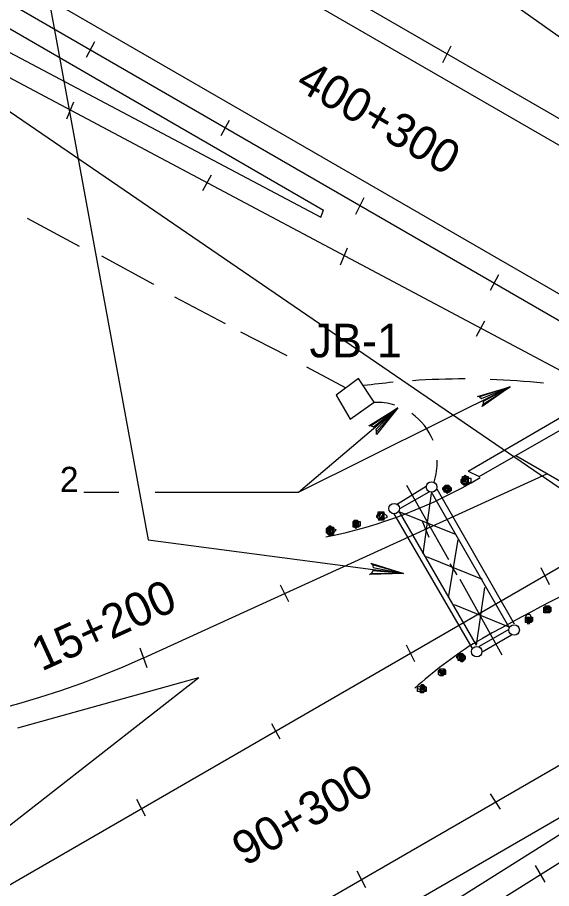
# Model space of a CAD drawing. Extents: x 36 to 2622, y -5330 to 219.
# Drawn here: x 2003.5 to 2051, y -4415.8 to -4338.2 of the extents above; entities that cross this region are included whole.
import ezdxf

# ---------------------------------------------------------------- set-up
doc = ezdxf.new("R2010")
doc.units = 0
doc.layers.add('2', color=7, linetype='Continuous')
doc.layers.add('3', color=7, linetype='Continuous')

# ---------------------------------------------------------------- blocks, each defined once
blk = doc.blocks.new('RARROW')
at = {"layer": '3'}
blk.add_lwpolyline([(-2.2695, 0.285), (-2.184875, 0.12075), (0, 0), (-2.2695, 0.285), (-2.38575, 0.384625), (0, 0), (-2.183125, -0.108), (-2.262875, -0.2705), (0, 0), (-2.38575, -0.379125), (-2.262875, -0.2705)], dxfattribs=at)

msp = doc.modelspace()

# ---------------------------------------------------------------- linework, layer by layer
at = {"layer": '2'}
for p, q in [((1732.847, -4161.874), (2538.009, -4712.774)), ((1828.856, -4218.455), (2074.481, -4360.33)), ((1984.731, -4219.33), (2015.106, -4384.705)), ((1827.856, -4220.205), (2072.731, -4361.705)), ((1822.106, -4230.205), (2060.856, -4368.08)), ((1820.981, -4231.955), (2055.231, -4367.205)), ((1954.606, -4443.205), (2241.981, -4277.33)), ((1905.981, -4283.33), (2030.731, -4355.33)), ((1962.231, -4456.455), (2237.606, -4297.455)), ((2078.106, -4358.705), (2040.356, -4331.83)), ((1996.856, -4338.205), (2030.481, -4355.955)), ((1995.981, -4339.955), (2055.481, -4371.58)), ((2009.606, -4341.705), (2010.356, -4340.33)), ((2041.356, -4342.205), (2042.106, -4340.705)), ((2007.856, -4347.205), (2008.481, -4345.705)), ((2021.606, -4348.705), (2022.356, -4347.33)), ((2043.606, -4378.58), (2091.606, -4350.705)), ((2044.606, -4379.08), (2092.731, -4351.455)), ((2019.981, -4353.58), (2020.731, -4352.205)), ((2033.606, -4355.705), (2034.356, -4354.205)), ((2030.481, -4355.955), (2030.731, -4355.33)), ((2008.981, -4358.58), (2004.356, -4356.08)), ((2032.231, -4360.205), (2032.856, -4358.705)), ((2015.606, -4361.955), (2010.981, -4359.455)), ((2045.606, -4362.455), (2046.356, -4361.08)), ((2021.981, -4365.455), (2017.481, -4363.08)), ((2044.356, -4366.58), (2045.106, -4365.205)), ((2027.481, -4368.33), (2023.356, -4366.205)), ((2032.731, -4371.205), (2029.231, -4369.33)), ((2028.481, -4380.455), (2047.356, -4371.08)), ((2028.481, -4380.455), (2037.356, -4372.955)), ((2047.856, -4377.205), (2061.231, -4384.955)), ((2014.731, -4395.205), (2050.606, -4378.83)), ((2043.606, -4378.58), (2044.606, -4379.08)), ((2038.106, -4379.83), (2041.856, -4386.455)), ((2009.356, -4380.455), (2012.481, -4380.455)), ((2015.731, -4380.455), (2028.481, -4380.455)), ((2039.856, -4379.955), (2037.231, -4381.58)), ((2040.106, -4380.455), (2037.481, -4381.955)), ((2039.606, -4385.955), (2040.356, -4380.58)), ((2047.231, -4392.455), (2040.356, -4380.455)), ((2047.731, -4392.205), (2040.856, -4380.205)), ((2044.356, -4394.08), (2037.481, -4382.205)), ((2037.481, -4382.205), (2042.481, -4384.205)), ((2043.981, -4394.33), (2036.981, -4382.33)), ((2039.481, -4382.955), (2040.106, -4384.455)), ((2015.106, -4384.705), (2037.856, -4387.705)), ((2041.856, -4389.83), (2042.731, -4384.705)), ((2039.856, -4386.205), (2044.856, -4388.205)), ((2041.981, -4386.83), (2042.606, -4387.83)), ((2050.856, -4388.705), (2050.106, -4387.205)), ((2042.856, -4388.205), (2046.606, -4394.955)), ((2026.856, -4388.705), (2027.606, -4390.205)), ((2044.356, -4394.08), (2045.106, -4388.955)), ((2042.356, -4390.455), (2047.231, -4392.455)), ((2047.231, -4392.705), (2044.606, -4394.205)), ((2047.481, -4393.205), (2044.856, -4394.705)), ((2014.356, -4394.33), (2014.981, -4396.08)), ((2038.856, -4395.58), (2038.106, -4394.08)), ((2038.356, -4421.83), (2080.856, -4395.205)), ((1999.606, -4412.58), (2019.606, -4396.955)), ((2003.481, -4401.455), (2019.606, -4396.955)), ((1964.356, -4459.955), (2068.356, -4399.83)), ((2037.231, -4420.08), (2068.606, -4400.33)), ((2026.856, -4402.455), (2026.106, -4401.08)), ((2014.856, -4409.33), (2014.106, -4407.83)), ((2046.481, -4408.705), (2045.606, -4407.33)), ((2050.481, -4415.205), (2049.606, -4413.705)), ((2034.481, -4415.705), (2033.731, -4414.205))]:
    msp.add_line(p, q, dxfattribs=at)
msp.add_lwpolyline([(2033.106, -4373.955), (2035.231, -4372.455), (2033.856, -4370.33), (2031.856, -4371.83)], close=True, dxfattribs=at)
for points in [[(2043.356, -4379.33), (2043.231, -4379.33), (2043.356, -4379.33), (2043.356, -4379.33), (2043.356, -4379.33), (2043.356, -4379.33), (2043.356, -4379.58), (2043.231, -4379.33), (2043.231, -4379.33), (2043.231, -4379.205), (2043.356, -4379.205), (2043.356, -4379.205), (2043.481, -4379.33), (2043.481, -4379.58), (2043.356, -4379.58), (2043.231, -4379.58), (2043.106, -4379.33), (2043.106, -4379.205), (2043.231, -4379.205), (2043.356, -4379.08), (2043.481, -4379.205), (2043.481, -4379.33), (2043.481, -4379.58), (2043.481, -4379.705), (2043.356, -4379.705), (2043.231, -4379.705), (2043.106, -4379.58), (2043.106, -4379.33), (2043.106, -4379.205), (2043.106, -4379.08), (2043.356, -4379.08), (2043.481, -4379.08), (2043.606, -4379.205), (2043.606, -4379.33), (2043.606, -4379.58), (2043.606, -4379.705), (2043.356, -4379.705), (2043.231, -4379.83), (2043.231, -4379.705), (2043.106, -4379.705), (2042.981, -4379.58), (2042.981, -4379.33), (2042.981, -4379.33), (2043.106, -4379.205), (2043.106, -4379.08), (2043.231, -4379.08), (2043.356, -4378.955), (2043.356, -4378.955), (2043.481, -4379.08), (2043.606, -4379.08), (2043.606, -4379.205), (2043.856, -4379.205), (2043.856, -4379.33), (2043.856, -4379.58), (2043.606, -4379.705), (2043.606, -4379.705), (2043.481, -4379.83), (2043.356, -4379.83), (2043.231, -4379.83), (2043.231, -4379.83), (2043.106, -4379.705)], [(2041.731, -4380.205), (2041.731, -4380.205), (2041.731, -4380.08), (2041.731, -4380.08), (2041.856, -4380.205), (2041.731, -4380.205), (2041.731, -4380.205), (2041.606, -4380.205), (2041.606, -4380.205), (2041.606, -4380.08), (2041.731, -4380.08), (2041.856, -4380.08), (2041.856, -4380.08), (2041.856, -4380.205), (2041.731, -4380.33), (2041.606, -4380.33), (2041.606, -4380.205), (2041.606, -4380.08), (2041.606, -4379.955), (2041.731, -4379.955), (2041.856, -4380.08), (2041.981, -4380.205), (2041.981, -4380.33), (2041.856, -4380.33), (2041.731, -4380.455), (2041.606, -4380.455), (2041.481, -4380.33), (2041.481, -4380.205), (2041.481, -4380.08), (2041.606, -4379.955), (2041.731, -4379.955), (2041.856, -4379.955), (2041.981, -4379.955), (2041.981, -4380.08), (2041.981, -4380.33), (2041.981, -4380.33), (2041.856, -4380.455), (2041.731, -4380.455), (2041.606, -4380.455), (2041.481, -4380.455), (2041.481, -4380.33), (2041.356, -4380.205), (2041.356, -4380.08), (2041.481, -4379.955), (2041.481, -4379.955), (2041.606, -4379.83), (2041.731, -4379.83), (2041.856, -4379.83), (2041.856, -4379.83), (2041.981, -4379.955), (2041.981, -4379.955), (2042.106, -4380.08), (2042.106, -4380.205), (2042.106, -4380.33), (2041.981, -4380.33), (2041.981, -4380.455), (2041.856, -4380.455), (2041.731, -4380.58), (2041.731, -4380.58), (2041.606, -4380.455), (2041.481, -4380.455)], [(2035.856, -4382.58), (2035.856, -4382.58), (2035.856, -4382.58), (2035.856, -4382.58), (2035.981, -4382.58), (2035.981, -4382.705), (2035.856, -4382.705), (2035.731, -4382.705), (2035.731, -4382.58), (2035.731, -4382.58), (2035.856, -4382.33), (2035.981, -4382.33), (2035.981, -4382.58), (2035.981, -4382.705), (2035.856, -4382.83), (2035.731, -4382.705), (2035.731, -4382.705), (2035.731, -4382.58), (2035.731, -4382.33), (2035.981, -4382.33), (2035.981, -4382.33), (2036.106, -4382.58), (2036.106, -4382.705), (2035.981, -4382.83), (2035.856, -4382.83), (2035.731, -4382.83), (2035.606, -4382.83), (2035.606, -4382.705), (2035.606, -4382.58), (2035.731, -4382.33), (2035.856, -4382.205), (2035.981, -4382.205), (2036.106, -4382.33), (2036.106, -4382.58), (2036.106, -4382.705), (2036.106, -4382.83), (2035.981, -4382.955), (2035.856, -4382.955), (2035.731, -4382.955), (2035.606, -4382.83), (2035.606, -4382.705), (2035.481, -4382.705), (2035.481, -4382.58), (2035.606, -4382.33), (2035.606, -4382.205), (2035.731, -4382.205), (2035.856, -4382.205), (2035.981, -4382.205), (2035.981, -4382.205), (2036.106, -4382.205), (2036.106, -4382.33), (2036.356, -4382.58), (2036.356, -4382.705), (2036.356, -4382.705), (2036.106, -4382.83), (2036.106, -4382.955), (2035.981, -4382.955), (2035.856, -4382.955), (2035.856, -4382.955), (2035.731, -4382.955), (2035.606, -4382.955)], [(2033.606, -4383.33), (2033.606, -4383.33), (2033.606, -4383.205), (2033.606, -4383.205), (2033.731, -4383.33), (2033.731, -4383.33), (2033.606, -4383.33), (2033.606, -4383.33), (2033.481, -4383.33), (2033.481, -4383.205), (2033.606, -4383.205), (2033.731, -4383.205), (2033.731, -4383.205), (2033.731, -4383.33), (2033.606, -4383.455), (2033.481, -4383.455), (2033.481, -4383.33), (2033.481, -4383.205), (2033.606, -4383.08), (2033.731, -4383.08), (2033.731, -4383.205), (2033.856, -4383.33), (2033.856, -4383.455), (2033.731, -4383.455), (2033.606, -4383.58), (2033.481, -4383.58), (2033.481, -4383.455), (2033.356, -4383.33), (2033.356, -4383.205), (2033.481, -4383.08), (2033.606, -4383.08), (2033.731, -4383.08), (2033.856, -4383.08), (2033.856, -4383.205), (2033.856, -4383.455), (2033.856, -4383.58), (2033.731, -4383.58), (2033.606, -4383.58), (2033.481, -4383.58), (2033.356, -4383.58), (2033.356, -4383.455), (2033.356, -4383.33), (2033.356, -4383.205), (2033.356, -4383.08), (2033.356, -4383.08), (2033.481, -4382.955), (2033.606, -4382.955), (2033.731, -4382.955), (2033.731, -4382.955), (2033.856, -4383.08), (2033.981, -4383.08), (2033.981, -4383.205), (2033.981, -4383.33), (2033.981, -4383.455), (2033.981, -4383.455), (2033.856, -4383.58), (2033.731, -4383.58), (2033.606, -4383.705), (2033.606, -4383.705), (2033.481, -4383.58), (2033.481, -4383.58)], [(2031.356, -4383.83), (2031.231, -4383.83), (2031.231, -4383.83), (2031.356, -4383.705), (2031.356, -4383.83), (2031.356, -4383.83), (2031.356, -4384.08), (2031.231, -4383.83), (2031.231, -4383.83), (2031.231, -4383.705), (2031.356, -4383.705), (2031.356, -4383.705), (2031.481, -4383.83), (2031.481, -4384.08), (2031.356, -4384.08), (2031.231, -4384.08), (2031.106, -4383.83), (2031.106, -4383.705), (2031.231, -4383.58), (2031.356, -4383.58), (2031.481, -4383.705), (2031.481, -4383.83), (2031.481, -4384.08), (2031.481, -4384.205), (2031.356, -4384.205), (2031.231, -4384.205), (2031.106, -4384.08), (2031.106, -4383.83), (2031.106, -4383.705), (2031.106, -4383.58), (2031.231, -4383.58), (2031.481, -4383.58), (2031.606, -4383.705), (2031.606, -4383.83), (2031.606, -4384.08), (2031.481, -4384.205), (2031.356, -4384.205), (2031.231, -4384.33), (2031.106, -4384.205), (2031.106, -4384.205), (2030.981, -4384.08), (2030.981, -4383.83), (2030.981, -4383.705), (2030.981, -4383.705), (2031.106, -4383.58), (2031.231, -4383.58), (2031.231, -4383.455), (2031.356, -4383.455), (2031.481, -4383.58), (2031.606, -4383.58), (2031.606, -4383.705), (2031.606, -4383.705), (2031.856, -4383.83), (2031.606, -4384.08), (2031.606, -4384.205), (2031.606, -4384.205), (2031.481, -4384.33), (2031.356, -4384.33), (2031.231, -4384.33), (2031.231, -4384.33), (2031.106, -4384.205)], [(2050.731, -4390.955), (2050.606, -4390.955), (2050.606, -4390.83), (2050.731, -4390.83), (2050.731, -4390.83), (2050.731, -4390.955), (2050.606, -4390.955), (2050.606, -4390.955), (2050.481, -4390.83), (2050.606, -4390.83), (2050.606, -4390.83), (2050.731, -4390.83), (2050.731, -4390.83), (2050.731, -4390.955), (2050.731, -4391.08), (2050.606, -4391.08), (2050.481, -4390.955), (2050.481, -4390.83), (2050.606, -4390.705), (2050.731, -4390.705), (2050.856, -4390.83), (2050.856, -4390.955), (2050.856, -4390.955), (2050.731, -4391.08), (2050.731, -4391.08), (2050.606, -4391.08), (2050.481, -4391.08), (2050.356, -4390.955), (2050.356, -4390.83), (2050.481, -4390.705), (2050.606, -4390.58), (2050.731, -4390.705), (2050.856, -4390.705), (2050.981, -4390.83), (2050.981, -4390.955), (2050.856, -4391.08), (2050.731, -4391.205), (2050.606, -4391.205), (2050.481, -4391.205), (2050.356, -4391.205), (2050.356, -4391.08), (2050.356, -4390.955), (2050.356, -4390.83), (2050.356, -4390.705), (2050.481, -4390.705), (2050.481, -4390.58), (2050.606, -4390.58), (2050.731, -4390.58), (2050.856, -4390.58), (2050.856, -4390.705), (2050.981, -4390.705), (2050.981, -4390.83), (2050.981, -4390.955), (2050.981, -4391.08), (2050.981, -4391.08), (2050.856, -4391.205), (2050.731, -4391.205), (2050.731, -4391.205), (2050.606, -4391.205), (2050.481, -4391.205), (2050.481, -4391.205)], [(2048.981, -4391.83), (2048.981, -4391.83), (2048.981, -4391.705), (2048.981, -4391.705), (2049.106, -4391.705), (2049.106, -4391.83), (2048.981, -4391.83), (2048.981, -4391.83), (2048.856, -4391.83), (2048.856, -4391.705), (2048.981, -4391.705), (2049.106, -4391.705), (2049.106, -4391.705), (2049.106, -4391.83), (2048.981, -4391.955), (2048.856, -4391.955), (2048.856, -4391.83), (2048.856, -4391.705), (2048.981, -4391.58), (2049.106, -4391.58), (2049.106, -4391.705), (2049.231, -4391.83), (2049.231, -4391.83), (2049.106, -4391.955), (2048.981, -4392.08), (2048.856, -4392.08), (2048.856, -4391.955), (2048.731, -4391.83), (2048.731, -4391.705), (2048.856, -4391.58), (2048.981, -4391.58), (2049.106, -4391.58), (2049.231, -4391.58), (2049.231, -4391.705), (2049.231, -4391.955), (2049.231, -4391.955), (2049.106, -4392.08), (2048.981, -4392.08), (2048.856, -4392.08), (2048.731, -4392.08), (2048.731, -4391.955), (2048.731, -4391.83), (2048.731, -4391.705), (2048.731, -4391.58), (2048.731, -4391.58), (2048.856, -4391.33), (2048.981, -4391.33), (2049.106, -4391.33), (2049.106, -4391.33), (2049.231, -4391.58), (2049.356, -4391.58), (2049.356, -4391.705), (2049.356, -4391.83), (2049.356, -4391.955), (2049.356, -4391.955), (2049.231, -4392.08), (2049.106, -4392.08), (2048.981, -4392.205), (2048.981, -4392.205), (2048.856, -4392.08), (2048.856, -4392.08)], [(2042.981, -4395.205), (2042.981, -4395.205), (2042.981, -4395.08), (2042.981, -4395.08), (2043.106, -4395.205), (2042.981, -4395.205), (2042.981, -4395.33), (2042.856, -4395.205), (2042.856, -4395.205), (2042.856, -4395.08), (2042.981, -4395.08), (2043.106, -4395.08), (2043.106, -4395.205), (2043.106, -4395.205), (2042.981, -4395.33), (2042.856, -4395.33), (2042.856, -4395.205), (2042.856, -4395.08), (2042.856, -4394.955), (2043.106, -4394.955), (2043.106, -4395.08), (2043.231, -4395.205), (2043.231, -4395.33), (2043.106, -4395.33), (2042.981, -4395.455), (2042.856, -4395.455), (2042.731, -4395.33), (2042.731, -4395.205), (2042.731, -4395.08), (2042.856, -4394.955), (2042.981, -4394.955), (2043.106, -4394.955), (2043.231, -4395.08), (2043.231, -4395.08), (2043.231, -4395.33), (2043.231, -4395.455), (2043.106, -4395.455), (2042.981, -4395.455), (2042.856, -4395.455), (2042.731, -4395.455), (2042.731, -4395.33), (2042.606, -4395.205), (2042.606, -4395.08), (2042.731, -4395.08), (2042.731, -4394.955), (2042.856, -4394.83), (2042.981, -4394.83), (2043.106, -4394.83), (2043.106, -4394.83), (2043.231, -4394.955), (2043.231, -4394.955), (2043.356, -4395.08), (2043.356, -4395.205), (2043.356, -4395.33), (2043.231, -4395.455), (2043.231, -4395.455), (2043.106, -4395.58), (2042.981, -4395.58), (2042.981, -4395.58), (2042.856, -4395.455), (2042.731, -4395.455)], [(2041.231, -4396.455), (2041.231, -4396.455), (2041.231, -4396.455), (2041.356, -4396.455), (2041.356, -4396.455), (2041.356, -4396.58), (2041.231, -4396.58), (2041.231, -4396.58), (2041.106, -4396.455), (2041.231, -4396.33), (2041.231, -4396.33), (2041.356, -4396.33), (2041.356, -4396.455), (2041.356, -4396.58), (2041.356, -4396.58), (2041.231, -4396.58), (2041.106, -4396.58), (2041.106, -4396.33), (2041.231, -4396.33), (2041.356, -4396.33), (2041.481, -4396.33), (2041.481, -4396.455), (2041.481, -4396.58), (2041.356, -4396.705), (2041.231, -4396.705), (2041.231, -4396.705), (2041.106, -4396.58), (2040.981, -4396.455), (2040.981, -4396.455), (2041.106, -4396.33), (2041.231, -4396.205), (2041.356, -4396.205), (2041.481, -4396.33), (2041.481, -4396.455), (2041.606, -4396.58), (2041.481, -4396.705), (2041.356, -4396.83), (2041.231, -4396.83), (2041.106, -4396.83), (2040.981, -4396.705), (2040.981, -4396.58), (2040.981, -4396.58), (2040.981, -4396.455), (2040.981, -4396.33), (2041.106, -4396.205), (2041.106, -4396.205), (2041.231, -4396.205), (2041.356, -4396.205), (2041.481, -4396.205), (2041.481, -4396.205), (2041.606, -4396.33), (2041.606, -4396.455), (2041.606, -4396.58), (2041.606, -4396.58), (2041.606, -4396.705), (2041.481, -4396.705), (2041.356, -4396.83), (2041.356, -4396.83), (2041.231, -4396.83), (2041.106, -4396.83), (2041.106, -4396.705)], [(2039.606, -4397.955), (2039.481, -4397.955), (2039.481, -4397.955), (2039.606, -4397.955), (2039.606, -4397.955), (2039.606, -4397.955), (2039.481, -4398.08), (2039.481, -4397.955), (2039.356, -4397.955), (2039.481, -4397.83), (2039.481, -4397.83), (2039.606, -4397.83), (2039.606, -4397.955), (2039.606, -4398.08), (2039.606, -4398.08), (2039.481, -4398.08), (2039.356, -4397.955), (2039.356, -4397.83), (2039.481, -4397.83), (2039.606, -4397.705), (2039.731, -4397.83), (2039.731, -4397.955), (2039.731, -4398.08), (2039.606, -4398.205), (2039.481, -4398.205), (2039.481, -4398.205), (2039.356, -4398.08), (2039.106, -4397.955), (2039.106, -4397.83), (2039.356, -4397.705), (2039.481, -4397.705), (2039.606, -4397.705), (2039.731, -4397.83), (2039.731, -4397.955), (2039.856, -4398.08), (2039.731, -4398.205), (2039.606, -4398.205), (2039.481, -4398.33), (2039.356, -4398.205), (2039.106, -4398.205), (2039.106, -4398.08), (2039.106, -4397.955), (2039.106, -4397.955), (2039.106, -4397.83), (2039.356, -4397.705), (2039.356, -4397.705), (2039.481, -4397.58), (2039.606, -4397.58), (2039.731, -4397.705), (2039.731, -4397.705), (2039.856, -4397.83), (2039.856, -4397.83), (2039.856, -4397.955), (2039.856, -4398.08), (2039.856, -4398.205), (2039.731, -4398.205), (2039.606, -4398.33), (2039.606, -4398.33), (2039.481, -4398.33), (2039.356, -4398.33), (2039.356, -4398.205)]]:
    msp.add_lwpolyline(points, dxfattribs=at)
for centre in [(2040.351, -4380.001), (2037.019, -4381.925), (2047.706, -4392.739), (2044.374, -4394.663)]:
    msp.add_circle(centre, 0.468, dxfattribs=at)
for centre, radius, start, end in [((2043.223, -4437.603), 67.224, 89.89238, 93.89942), ((2043.223, -4437.603), 67.224, 83.94899, 87.99585), ((2043.223, -4437.603), 67.224, 95.36917, 97.62254), ((2035.488, -4377.835), 5.369, 72.67596, 92.8594), ((2035.488, -4377.835), 5.369, 21.58093, 54.64075), ((2035.488, -4377.835), 5.369, 341.27246, 2.46719), ((2022.349, -4341.703), 43.601, 281.34732, 300.8001), ((2128.415, -4541.435), 169.896, 114.49576, 119.77299), ((2065.883, -4427.964), 40.405, 122.70697, 131.97575), ((1982.505, -4324.652), 77.546, 248.18068, 294.51902)]:
    msp.add_arc(centre, radius, start, end, dxfattribs=at)

# ---------------------------------------------------------------- block references
at = {"layer": '2', "xscale": 1.2574347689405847, "yscale": 1.3092961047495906}
for p, rotation in [((2047.356, -4371.079), 25.759934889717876), ((2037.356, -4372.954), 41.39136906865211), ((2037.856, -4387.704), -7.929121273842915)]:
    msp.add_blockref('RARROW', p, dxfattribs=dict(at, rotation=rotation))

# ---------------------------------------------------------------- texts
at = {"layer": '2'}
for s, height, rotation, p in [('400+300', 3, 329.99957, (2028.106, -4344.454)), ('2', 2.25, 0.00545, (2007.231, -4380.454)), ('15+200', 3, 24.51839, (2005.606, -4396.454)), ('90+300', 3, 30, (2023.731, -4413.829))]:
    msp.add_text(s, height=height, rotation=rotation, dxfattribs=at).set_placement(p)
msp.add_text('JB-1', height=2.9955, dxfattribs=at).set_placement((2029.481, -4368.454))

doc.saveas('drawing.dxf')
